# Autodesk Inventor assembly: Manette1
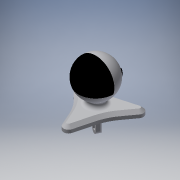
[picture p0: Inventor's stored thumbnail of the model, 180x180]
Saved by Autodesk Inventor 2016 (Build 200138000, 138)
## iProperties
Created: 2013-10
Part Number: Manette1
Material: Générique
Document SubType Name: Assembly
Designer: Bruno
Author: Bruno
Sending System: SolidWorks 2013
Last Author: christophe
Last Saved: 2014-02-15
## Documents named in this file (3)
- D:\Cours\Systèmes SI\Robot Haptique\Documentations_pedagogique\Modèle solidworks\Réel\Manette1.iam
- D:\Cours\Systèmes SI\Robot Haptique\Documentations_pedagogique\Modèle solidworks\Réel\manette.iam
- D:\Cours\Systèmes SI\Robot Haptique\Documentations_pedagogique\Modèle solidworks\Réel\manette2.ipt
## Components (2 placed, 2 different names)
1. manette:1 [sub-assembly]
2. manette2:1
